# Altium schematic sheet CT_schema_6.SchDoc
size 287 x 160 mm
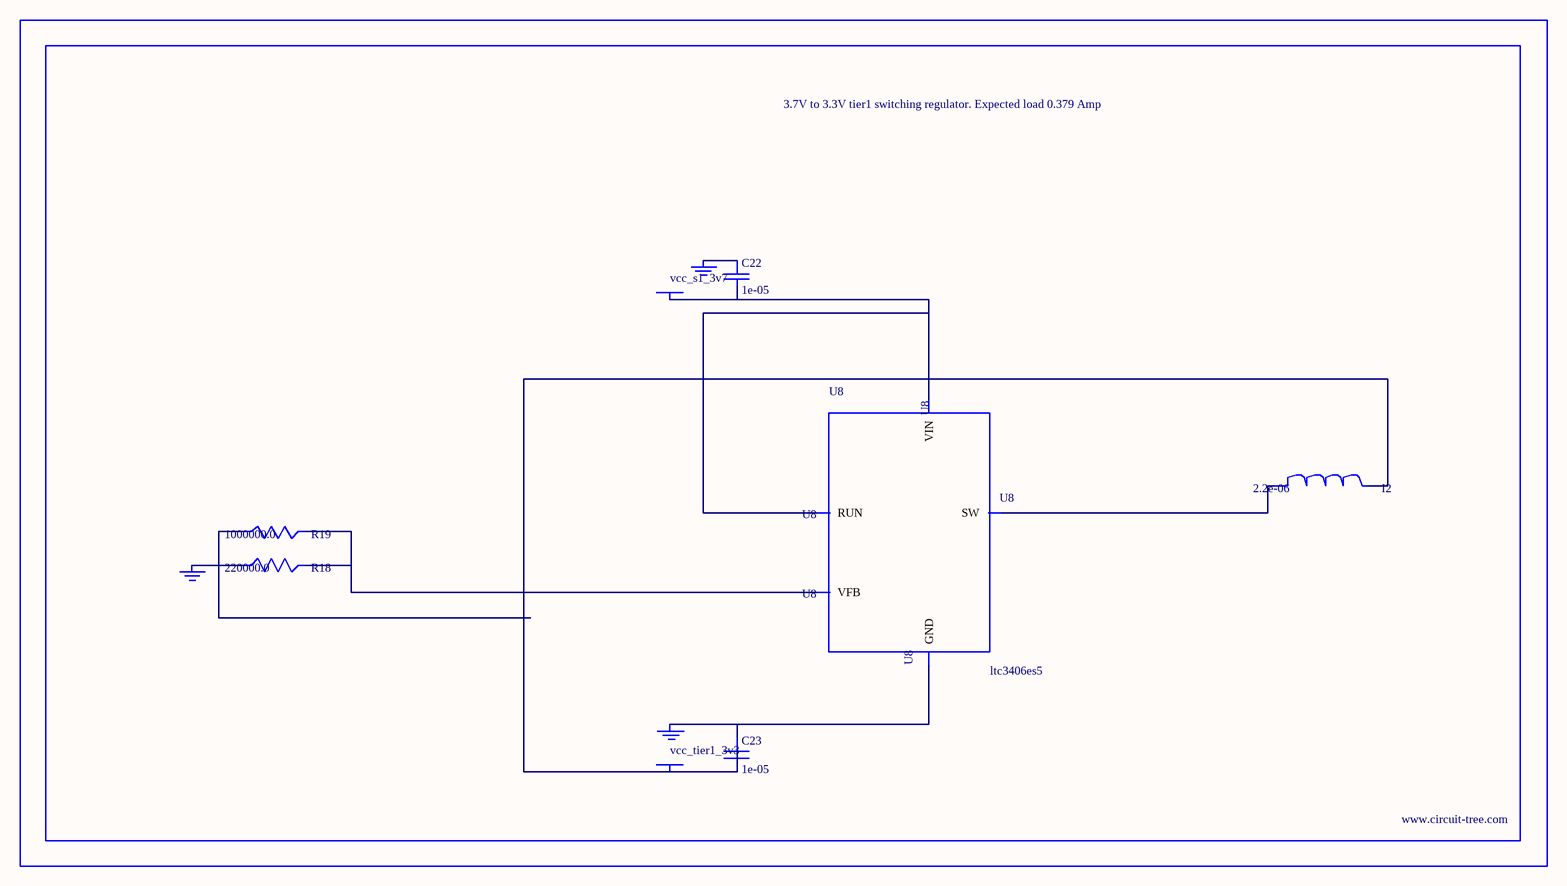
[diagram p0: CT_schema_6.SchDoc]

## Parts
BORDER5  (no value)
C22  1e-05  [C0805]
C23  1e-05  [C0805]
GND_INSTANCE_5_0  (no value)
GND_INSTANCE_5_1  (no value)
GND_INSTANCE_5_2  (no value)
I2  2.2e-06  [L0805]
POWER_INSTANCE_5_0  vcc_tier1_3v3
POWER_INSTANCE_5_1  vcc_s1_3v7
R18  220000.0  [R0603]
R19  1000000.0  [R0603]
U8  ltc3406es5  [TSOT-23-5]

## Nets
NetC22_1: C22.1 GND_INSTANCE_5_1.0(GND)
NetC22_2: C22.2 POWER_INSTANCE_5_1.0(PWR) U8.1(RUN) U8.4(VIN)
NetC23_1: C23.1 GND_INSTANCE_5_0.0(GND) U8.2(GND)
NetC23_2: C23.2 I2.2 POWER_INSTANCE_5_0.0(PWR) R19.1
NetGND_INSTANCE_5_2_0: GND_INSTANCE_5_2.0(GND) R18.1
NetI2_1: I2.1 U8.3(SW)
NetR18_2: R18.2 R19.2 U8.5(VFB)

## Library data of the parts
BORDER5 = BORDER_PAGE5
C22 C23 = C0805C106K8RACTU
GND_INSTANCE_5_0-GND_INSTANCE_5_2 = GND
I2 = L0805C2R2MDWIT
POWER_INSTANCE_5_0 POWER_INSTANCE_5_1 = PWR
R18 = RC0603JR-07220KL
R19 = RC0603JR-071ML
